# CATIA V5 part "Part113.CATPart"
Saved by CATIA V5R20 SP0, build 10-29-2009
Part number: FA 063200-1
Revision: ANY
Definition: UNKNOWN
Nomenclature: FA 063200-1
Source: Unknown
Bounding box of the stored display mesh (mm): x -2.5 to 2.5, y 0.15 to 2.5, z -2.5 to 2.5
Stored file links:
  C:\Users\Utente\Desktop\IO LAVORO\3D X SITO CF\CUMSA\3D files FA\FA 063212-21\Part113.CATPart

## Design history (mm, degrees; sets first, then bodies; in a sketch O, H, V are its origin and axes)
Body1 "Cortar-Extruir1" (main body)
  Solid1: solid without history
